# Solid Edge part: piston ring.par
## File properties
Author: Vicky Raina
Template: Normal.par
Last saved by: Robert a Rhodes jr
Revision: 4
Application: Solid Edge
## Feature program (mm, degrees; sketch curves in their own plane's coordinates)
sketch for "unnamed Protrusion 1" #1 plane through (0, 0, 0) normal (0, 0, 1) x-axis (1, 0, 0)
  circle centre (0, 0) radius 42.5
sketch for "unnamed Protrusion 1" #2 plane through (0, 0, 0) normal (0, 0, 1) x-axis (1, 0, 0)
  circle centre (0, 0) radius 46.5
extrude "unnamed Protrusion 1" add finite 3 along -normal
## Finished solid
Body 1: solid body, 4 faces, 4 edges, 0 vertices.
  Faces by surface: cylinder 2, plane 2
  Edges by curve: circle 4
Bounding box of the edges (mm): 93.000 x 93.000 x 3.000, from (-46.5, -46.5, -3) to (46.5, 46.5, 0).
Cylindrical faces by radius (mm): R42.5 x1, R46.5 x1
Planar faces by outward normal: +z 1, -z 1
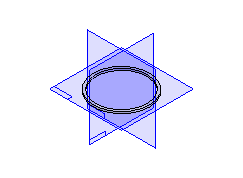
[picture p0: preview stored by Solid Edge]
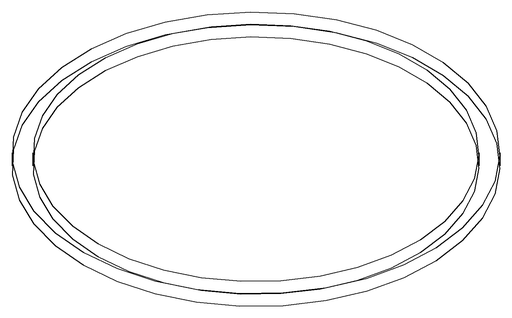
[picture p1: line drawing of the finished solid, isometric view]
